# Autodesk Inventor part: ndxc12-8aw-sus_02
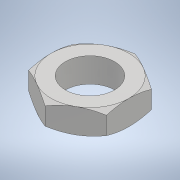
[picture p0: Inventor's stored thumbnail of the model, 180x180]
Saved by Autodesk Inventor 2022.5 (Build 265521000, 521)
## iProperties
Part Number: ndxc12-8aw-sus_02
Material: 一般
Document SubType Name: Modeling
Designer: ImaoCorp
Density: 1 g/cm^3
Appearance: 既定
Author: ImaoCorp
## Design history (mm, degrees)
feature "ndxc12-8aw-sus_02"
node "ソリッド1"
